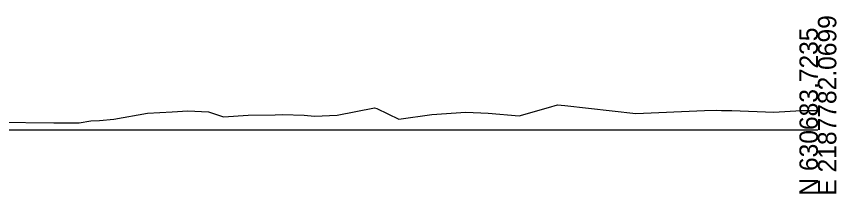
# Model space of a CAD drawing. Extents: x -26 to 4903, y -1010 to 9587.
# Drawn here: x 1178.2 to 1302.8, y 2990.3 to 3017.3 of the extents above; entities that cross this region are included whole.
import ezdxf

# ---------------------------------------------------------------- set-up
doc = ezdxf.new("R2010")
doc.units = 0
doc.layers.add('Exist Cross Section Cell', color=7, linetype='Continuous')
doc.layers.add('Exist XS Ground Line', color=7, linetype='Continuous')

msp = doc.modelspace()

# ---------------------------------------------------------------- linework, layer by layer
at = {"layer": 'Exist Cross Section Cell'}
msp.add_line((1150, 3000), (1300, 3000), dxfattribs=at)
at = {"layer": 'Exist XS Ground Line'}
for p, q in [((1198.16, 3002.55), (1201.9, 3002.75)), ((1201.9, 3002.75), (1204.31, 3002.93)), ((1204.31, 3002.93), (1207.44, 3002.75)), ((1207.44, 3002.75), (1209.73, 3001.99)), ((1226.99, 3002.26), (1232.65, 3003.38)), ((1232.65, 3003.38), (1233, 3003.29)), ((1233, 3003.29), (1236.35, 3001.66)), ((1241.37, 3002.36), (1246.51, 3002.7)), ((1246.51, 3002.7), (1249.93, 3002.56)), ((1254.64, 3002.16), (1259.08, 3003.42)), ((1259.08, 3003.42), (1260.44, 3003.82)), ((1260.44, 3003.82), (1261.56, 3003.74)), ((1261.56, 3003.74), (1272.34, 3002.53)), ((1272.34, 3002.53), (1282.76, 3002.95)), ((1282.76, 3002.95), (1284.62, 3003.02)), ((1284.62, 3003.02), (1285.34, 3002.95)), ((1285.34, 3002.95), (1286.95, 3002.96)), ((1286.95, 3002.96), (1293.32, 3002.72)), ((1293.32, 3002.72), (1297.44, 3002.99)), ((1297.44, 3002.99), (1298.6, 3002.97)), ((1298.6, 3002.97), (1300, 3002.96)), ((1189.53, 3001.39), (1190.86, 3001.45)), ((1190.86, 3001.45), (1193.06, 3001.66)), ((1193.06, 3001.66), (1198.16, 3002.55)), ((1209.73, 3001.99), (1213.47, 3002.24)), ((1213.47, 3002.24), (1217.55, 3002.29)), ((1217.55, 3002.29), (1218.66, 3002.34)), ((1218.66, 3002.34), (1221.94, 3002.28)), ((1221.94, 3002.28), (1223.51, 3002.12)), ((1223.51, 3002.12), (1226.99, 3002.26)), ((1236.35, 3001.66), (1241.37, 3002.36)), ((1249.93, 3002.56), (1254.64, 3002.16)), ((1173.83, 3001.19), (1183.95, 3001.11)), ((1183.95, 3001.11), (1185.87, 3001.11)), ((1185.87, 3001.11), (1187.79, 3001.11)), ((1187.79, 3001.11), (1189.53, 3001.39))]:
    msp.add_line(p, q, dxfattribs=at)

# ---------------------------------------------------------------- texts
at = {"layer": 'Exist Cross Section Cell'}
for s, p in [('E 2187782.0699', (1302.8, 2990)), ('N 630683.7235', (1300, 2990))]:
    msp.add_text(s, height=2.8, rotation=90, dxfattribs=at).set_placement(p)

doc.saveas('drawing.dxf')
